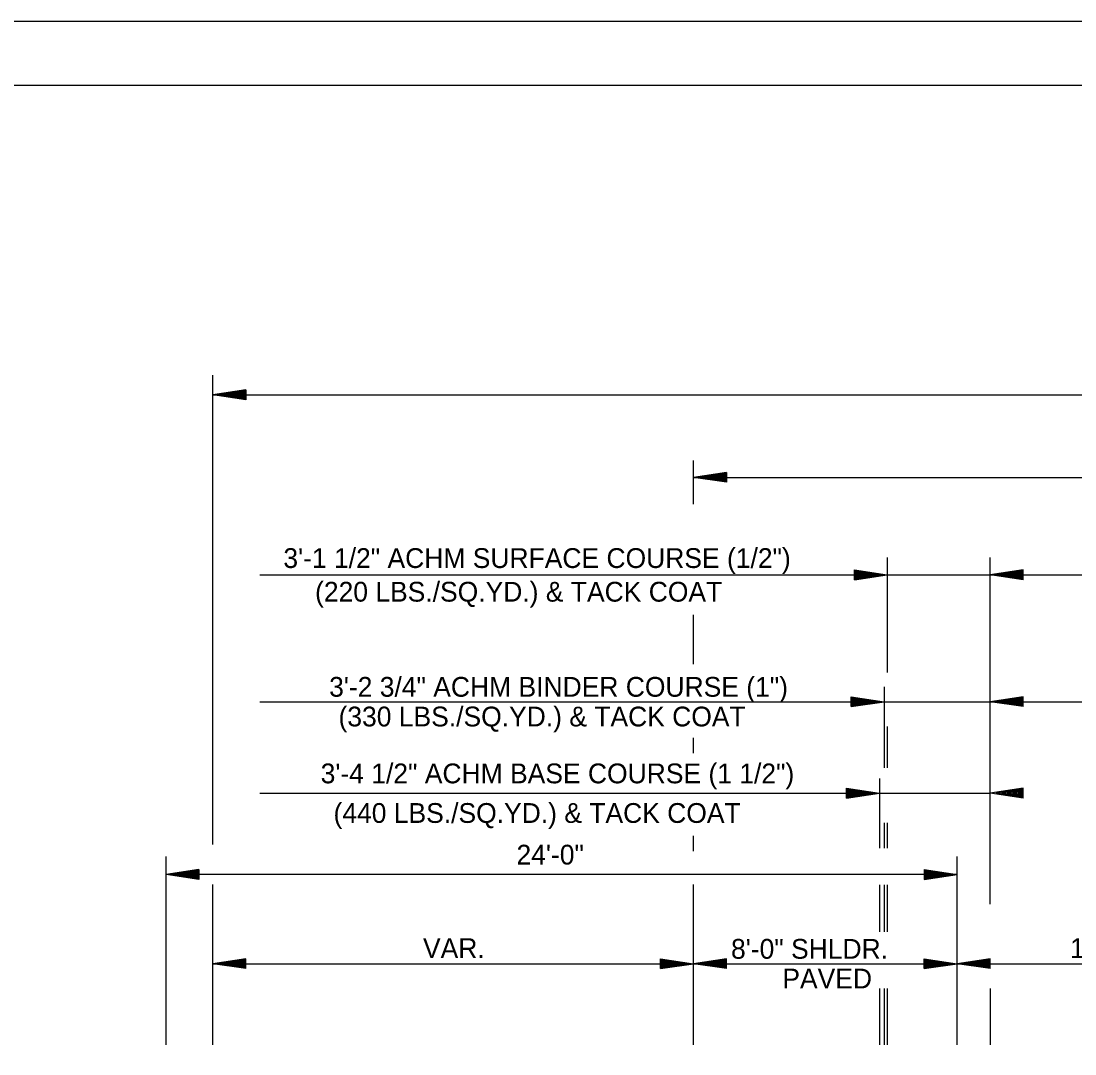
# Model space of a CAD drawing. Extents: x 1371763 to 1372860, y 385599 to 385872.
# Drawn here: x 1372519.52 to 1372551.49, y 385673.94 to 385705.25 of the extents above; entities that cross this region are included whole.
import ezdxf

# ---------------------------------------------------------------- set-up
doc = ezdxf.new("R2010")
doc.units = 0
for name, color, linetype in [('R_Border', 7, 'Continuous'), ('R_Draft', 7, 'Continuous'), ('R_No Plot', 7, 'Continuous')]:
    doc.layers.add(name, color=color, linetype=linetype)

msp = doc.modelspace()

# ---------------------------------------------------------------- linework, layer by layer
at = {"layer": 'R_Border'}
msp.add_line((1372499.208, 385703.307), (1372657.298, 385703.307), dxfattribs=at)
at = {"layer": 'R_Draft'}
for p, q in [((1372525.346, 385680.287), (1372525.346, 385694.519)), ((1372526.346, 385694.069), (1372525.346, 385693.919)), ((1372526.346, 385694.044), (1372525.513, 385693.919)), ((1372526.346, 385694.018), (1372525.685, 385693.919)), ((1372526.346, 385693.993), (1372525.852, 385693.919)), ((1372526.346, 385693.967), (1372526.021, 385693.919)), ((1372526.346, 385694.069), (1372526.346, 385693.769)), ((1372525.346, 385693.919), (1372591.103, 385693.919)), ((1372526.346, 385693.769), (1372525.346, 385693.919)), ((1372526.346, 385693.794), (1372525.513, 385693.919)), ((1372526.346, 385693.819), (1372525.685, 385693.919)), ((1372526.346, 385693.844), (1372525.852, 385693.919)), ((1372526.346, 385693.87), (1372526.021, 385693.919)), ((1372526.346, 385693.942), (1372526.188, 385693.919)), ((1372526.346, 385693.895), (1372526.188, 385693.919)), ((1372539.919, 385690.609), (1372539.919, 385691.929)), ((1372540.919, 385691.569), (1372539.919, 385691.419)), ((1372539.919, 385691.419), (1372579.918, 385691.419)), ((1372540.919, 385691.269), (1372539.919, 385691.419)), ((1372540.919, 385691.544), (1372540.086, 385691.419)), ((1372540.919, 385691.294), (1372540.086, 385691.419)), ((1372540.919, 385691.518), (1372540.258, 385691.419)), ((1372540.919, 385691.319), (1372540.258, 385691.419)), ((1372540.919, 385691.493), (1372540.424, 385691.419)), ((1372540.919, 385691.344), (1372540.424, 385691.419)), ((1372540.919, 385691.467), (1372540.594, 385691.419)), ((1372540.919, 385691.37), (1372540.594, 385691.419)), ((1372540.919, 385691.442), (1372540.761, 385691.419)), ((1372540.919, 385691.395), (1372540.761, 385691.419)), ((1372540.919, 385691.569), (1372540.919, 385691.269)), ((1372545.801, 385688.988), (1372545.801, 385685.506)), ((1372548.921, 385678.474), (1372548.923, 385688.988)), ((1372544.801, 385688.613), (1372545.801, 385688.463)), ((1372544.801, 385688.313), (1372544.801, 385688.613)), ((1372544.801, 385688.588), (1372545.634, 385688.463)), ((1372544.801, 385688.562), (1372545.462, 385688.463)), ((1372544.801, 385688.537), (1372545.295, 385688.463)), ((1372549.923, 385688.613), (1372548.923, 385688.463)), ((1372549.923, 385688.588), (1372549.09, 385688.463)), ((1372549.923, 385688.562), (1372549.262, 385688.463)), ((1372549.923, 385688.537), (1372549.428, 385688.463)), ((1372549.923, 385688.313), (1372549.923, 385688.613)), ((1372526.764, 385688.462), (1372548.923, 385688.463)), ((1372544.801, 385688.512), (1372545.126, 385688.463)), ((1372544.801, 385688.486), (1372544.959, 385688.463)), ((1372544.801, 385688.313), (1372545.801, 385688.463)), ((1372544.801, 385688.414), (1372545.126, 385688.463)), ((1372544.801, 385688.363), (1372545.462, 385688.463)), ((1372544.801, 385688.338), (1372545.634, 385688.463)), ((1372544.801, 385688.388), (1372545.295, 385688.463)), ((1372544.801, 385688.439), (1372544.959, 385688.463)), ((1372548.923, 385688.463), (1372570.923, 385688.463)), ((1372549.923, 385688.313), (1372548.923, 385688.463)), ((1372549.923, 385688.338), (1372549.09, 385688.463)), ((1372549.923, 385688.363), (1372549.262, 385688.463)), ((1372549.923, 385688.388), (1372549.428, 385688.463)), ((1372549.923, 385688.512), (1372549.598, 385688.463)), ((1372549.923, 385688.414), (1372549.598, 385688.463)), ((1372549.923, 385688.486), (1372549.765, 385688.463)), ((1372549.923, 385688.439), (1372549.765, 385688.463)), ((1372539.921, 385685.755), (1372539.921, 385687.255)), ((1372545.702, 385685.068), (1372545.702, 385682.617)), ((1372544.702, 385684.768), (1372545.702, 385684.618)), ((1372544.702, 385684.468), (1372544.702, 385684.768)), ((1372544.702, 385684.743), (1372545.535, 385684.618)), ((1372544.702, 385684.718), (1372545.363, 385684.618)), ((1372544.702, 385684.693), (1372545.196, 385684.618)), ((1372549.923, 385684.768), (1372548.923, 385684.618)), ((1372549.923, 385684.743), (1372549.09, 385684.618)), ((1372549.923, 385684.718), (1372549.262, 385684.618)), ((1372549.923, 385684.693), (1372549.428, 385684.618)), ((1372549.923, 385684.468), (1372549.923, 385684.768)), ((1372526.764, 385684.618), (1372548.923, 385684.618)), ((1372544.702, 385684.667), (1372545.027, 385684.618)), ((1372544.702, 385684.642), (1372544.86, 385684.618)), ((1372544.702, 385684.468), (1372545.702, 385684.618)), ((1372544.702, 385684.57), (1372545.027, 385684.618)), ((1372544.702, 385684.519), (1372545.363, 385684.618)), ((1372544.702, 385684.493), (1372545.535, 385684.618)), ((1372544.702, 385684.544), (1372545.196, 385684.618)), ((1372544.702, 385684.595), (1372544.86, 385684.618)), ((1372549.923, 385684.468), (1372548.923, 385684.618)), ((1372548.923, 385684.618), (1372570.923, 385684.618)), ((1372549.923, 385684.493), (1372549.09, 385684.618)), ((1372549.923, 385684.519), (1372549.262, 385684.618)), ((1372549.923, 385684.544), (1372549.428, 385684.618)), ((1372549.923, 385684.667), (1372549.598, 385684.618)), ((1372549.923, 385684.57), (1372549.598, 385684.618)), ((1372549.923, 385684.642), (1372549.765, 385684.618)), ((1372549.923, 385684.595), (1372549.765, 385684.618)), ((1372545.801, 385683.868), (1372545.801, 385682.617)), ((1372539.921, 385683.057), (1372539.921, 385683.523)), ((1372545.563, 385682.293), (1372545.563, 385680.178)), ((1372526.764, 385681.843), (1372548.923, 385681.843)), ((1372544.563, 385681.993), (1372545.563, 385681.843)), ((1372544.563, 385681.693), (1372544.563, 385681.993)), ((1372544.563, 385681.968), (1372545.396, 385681.843)), ((1372544.563, 385681.943), (1372545.224, 385681.843)), ((1372544.563, 385681.918), (1372545.057, 385681.843)), ((1372544.563, 385681.892), (1372544.888, 385681.843)), ((1372544.563, 385681.867), (1372544.721, 385681.843)), ((1372544.563, 385681.693), (1372545.563, 385681.843)), ((1372544.563, 385681.795), (1372544.888, 385681.843)), ((1372544.563, 385681.744), (1372545.224, 385681.843)), ((1372544.563, 385681.718), (1372545.396, 385681.843)), ((1372544.563, 385681.769), (1372545.057, 385681.843)), ((1372544.563, 385681.82), (1372544.721, 385681.843)), ((1372549.922, 385681.993), (1372548.922, 385681.843)), ((1372549.922, 385681.693), (1372548.922, 385681.843)), ((1372549.922, 385681.968), (1372549.089, 385681.843)), ((1372549.922, 385681.718), (1372549.089, 385681.843)), ((1372549.922, 385681.943), (1372549.261, 385681.843)), ((1372549.922, 385681.744), (1372549.261, 385681.843)), ((1372549.922, 385681.918), (1372549.427, 385681.843)), ((1372549.922, 385681.769), (1372549.427, 385681.843)), ((1372549.922, 385681.892), (1372549.597, 385681.843)), ((1372549.922, 385681.795), (1372549.597, 385681.843)), ((1372549.922, 385681.867), (1372549.764, 385681.843)), ((1372549.922, 385681.82), (1372549.764, 385681.843)), ((1372549.922, 385681.693), (1372549.922, 385681.993)), ((1372545.702, 385680.943), (1372545.702, 385680.178)), ((1372545.801, 385680.943), (1372545.801, 385680.178)), ((1372539.921, 385680.084), (1372539.921, 385680.549)), ((1372523.921, 385674.212), (1372523.921, 385679.921)), ((1372547.92, 385674.209), (1372547.921, 385679.921)), ((1372524.921, 385679.53), (1372523.921, 385679.38)), ((1372524.921, 385679.23), (1372523.921, 385679.38)), ((1372547.921, 385679.38), (1372523.921, 385679.38)), ((1372524.921, 385679.505), (1372524.088, 385679.38)), ((1372524.921, 385679.255), (1372524.088, 385679.38)), ((1372524.921, 385679.48), (1372524.26, 385679.38)), ((1372524.921, 385679.281), (1372524.26, 385679.38)), ((1372524.921, 385679.455), (1372524.426, 385679.38)), ((1372524.921, 385679.306), (1372524.426, 385679.38)), ((1372524.921, 385679.429), (1372524.596, 385679.38)), ((1372524.921, 385679.331), (1372524.596, 385679.38)), ((1372524.921, 385679.404), (1372524.763, 385679.38)), ((1372524.921, 385679.357), (1372524.763, 385679.38)), ((1372524.921, 385679.53), (1372524.921, 385679.23)), ((1372546.921, 385679.53), (1372547.921, 385679.38)), ((1372546.921, 385679.53), (1372546.921, 385679.23)), ((1372546.921, 385679.505), (1372547.754, 385679.38)), ((1372546.921, 385679.48), (1372547.582, 385679.38)), ((1372546.921, 385679.455), (1372547.415, 385679.38)), ((1372546.921, 385679.429), (1372547.246, 385679.38)), ((1372546.921, 385679.404), (1372547.079, 385679.38)), ((1372546.921, 385679.23), (1372547.921, 385679.38)), ((1372546.921, 385679.331), (1372547.246, 385679.38)), ((1372546.921, 385679.281), (1372547.582, 385679.38)), ((1372546.921, 385679.255), (1372547.754, 385679.38)), ((1372546.921, 385679.306), (1372547.415, 385679.38)), ((1372546.921, 385679.357), (1372547.079, 385679.38)), ((1372525.345, 385674.212), (1372525.346, 385679.072)), ((1372539.92, 385674.211), (1372539.921, 385679.071)), ((1372545.563, 385679.07), (1372545.563, 385677.643)), ((1372545.702, 385679.07), (1372545.702, 385677.643)), ((1372545.801, 385679.07), (1372545.801, 385677.643)), ((1372526.346, 385676.824), (1372525.346, 385676.674)), ((1372526.346, 385676.799), (1372525.513, 385676.674)), ((1372526.346, 385676.773), (1372525.685, 385676.674)), ((1372526.346, 385676.748), (1372525.851, 385676.674)), ((1372526.346, 385676.723), (1372526.021, 385676.674)), ((1372526.346, 385676.524), (1372526.346, 385676.824)), ((1372538.92, 385676.824), (1372539.92, 385676.674)), ((1372538.92, 385676.524), (1372538.92, 385676.824)), ((1372538.92, 385676.799), (1372539.753, 385676.674)), ((1372538.92, 385676.773), (1372539.581, 385676.674)), ((1372538.92, 385676.748), (1372539.415, 385676.674)), ((1372538.92, 385676.723), (1372539.245, 385676.674)), ((1372540.921, 385676.824), (1372539.921, 385676.674)), ((1372540.921, 385676.799), (1372540.088, 385676.674)), ((1372540.921, 385676.773), (1372540.26, 385676.674)), ((1372540.921, 385676.748), (1372540.426, 385676.674)), ((1372540.921, 385676.723), (1372540.596, 385676.674)), ((1372540.921, 385676.524), (1372540.921, 385676.824)), ((1372546.921, 385676.824), (1372547.921, 385676.674)), ((1372546.921, 385676.524), (1372546.921, 385676.824)), ((1372546.921, 385676.799), (1372547.754, 385676.674)), ((1372546.921, 385676.773), (1372547.582, 385676.674)), ((1372546.921, 385676.748), (1372547.415, 385676.674)), ((1372546.921, 385676.723), (1372547.246, 385676.674)), ((1372548.921, 385676.824), (1372547.921, 385676.674)), ((1372548.921, 385676.799), (1372548.088, 385676.674)), ((1372548.921, 385676.773), (1372548.26, 385676.674)), ((1372548.921, 385676.748), (1372548.426, 385676.674)), ((1372548.921, 385676.723), (1372548.596, 385676.674)), ((1372548.921, 385676.524), (1372548.921, 385676.824)), ((1372525.346, 385676.674), (1372539.92, 385676.674)), ((1372526.346, 385676.524), (1372525.346, 385676.674)), ((1372526.346, 385676.549), (1372525.513, 385676.674)), ((1372526.346, 385676.574), (1372525.685, 385676.674)), ((1372526.346, 385676.599), (1372525.851, 385676.674)), ((1372526.346, 385676.625), (1372526.021, 385676.674)), ((1372526.346, 385676.697), (1372526.188, 385676.674)), ((1372526.346, 385676.65), (1372526.188, 385676.674)), ((1372538.92, 385676.697), (1372539.078, 385676.674)), ((1372538.92, 385676.524), (1372539.92, 385676.674)), ((1372538.92, 385676.625), (1372539.245, 385676.674)), ((1372538.92, 385676.574), (1372539.581, 385676.674)), ((1372538.92, 385676.549), (1372539.753, 385676.674)), ((1372538.92, 385676.599), (1372539.415, 385676.674)), ((1372538.92, 385676.65), (1372539.078, 385676.674)), ((1372539.921, 385676.674), (1372547.921, 385676.674)), ((1372540.921, 385676.524), (1372539.921, 385676.674)), ((1372540.921, 385676.549), (1372540.088, 385676.674)), ((1372540.921, 385676.574), (1372540.26, 385676.674)), ((1372540.921, 385676.599), (1372540.426, 385676.674)), ((1372540.921, 385676.625), (1372540.596, 385676.674)), ((1372540.921, 385676.697), (1372540.763, 385676.674)), ((1372540.921, 385676.65), (1372540.763, 385676.674)), ((1372546.921, 385676.697), (1372547.079, 385676.674)), ((1372546.921, 385676.524), (1372547.921, 385676.674)), ((1372546.921, 385676.625), (1372547.246, 385676.674)), ((1372546.921, 385676.574), (1372547.582, 385676.674)), ((1372546.921, 385676.549), (1372547.754, 385676.674)), ((1372546.921, 385676.599), (1372547.415, 385676.674)), ((1372546.921, 385676.65), (1372547.079, 385676.674)), ((1372547.921, 385676.674), (1372559.921, 385676.674)), ((1372548.921, 385676.524), (1372547.921, 385676.674)), ((1372548.921, 385676.549), (1372548.088, 385676.674)), ((1372548.921, 385676.574), (1372548.26, 385676.674)), ((1372548.921, 385676.599), (1372548.426, 385676.674)), ((1372548.921, 385676.625), (1372548.596, 385676.674)), ((1372548.921, 385676.697), (1372548.763, 385676.674)), ((1372548.921, 385676.65), (1372548.763, 385676.674)), ((1372545.563, 385675.924), (1372545.563, 385674.21)), ((1372545.702, 385675.924), (1372545.702, 385674.21)), ((1372545.801, 385675.924), (1372545.801, 385674.21)), ((1372548.921, 385675.924), (1372548.921, 385674.209))]:
    msp.add_line(p, q, dxfattribs=at)
at = {"layer": 'R_No Plot'}
msp.add_line((1372493.007, 385705.254), (1372659.674, 385705.254), dxfattribs=at)
for points in [[(1372493.004, 385705.254), (1372659.674, 385705.254), (1372659.674, 385598.585), (1372493.004, 385598.585)], [(1372616.168, 385703.307), (1372625.978, 385703.307), (1372625.978, 385698.367), (1372634.034, 385698.367), (1372645.634, 385698.367), (1372645.634, 385682.032), (1372657.238, 385682.032), (1372657.298, 385600.577), (1372499.208, 385600.577), (1372499.208, 385703.307)]]:
    msp.add_lwpolyline(points, close=True, dxfattribs=at)

# ---------------------------------------------------------------- texts
at = {"layer": 'R_Draft'}
for s, p in [('3\'-1 1/2" ACHM SURFACE COURSE (1/2")', (1372527.481, 385688.672)), ('(220 LBS./SQ.YD.) & TACK COAT', (1372528.442, 385687.652)), ('3\'-2 3/4" ACHM BINDER COURSE (1")', (1372528.869, 385684.768)), ('(330 LBS./SQ.YD.) & TACK COAT', (1372529.154, 385683.868)), ('3\'-4 1/2" ACHM BASE COURSE (1 1/2")', (1372528.612, 385682.143)), ('(440 LBS./SQ.YD.) & TACK COAT', (1372529.002, 385680.943)), ('24\'-0"', (1372534.553, 385679.68)), ('VAR.', (1372531.716, 385676.845)), ('8\'-0" SHLDR.', (1372541.06, 385676.824)), ('12\'-0" LANE', (1372551.343, 385676.845)), ('PAVED', (1372542.617, 385675.924))]:
    msp.add_text(s, height=0.6, rotation=360, dxfattribs=at).set_placement(p)

doc.saveas('drawing.dxf')
